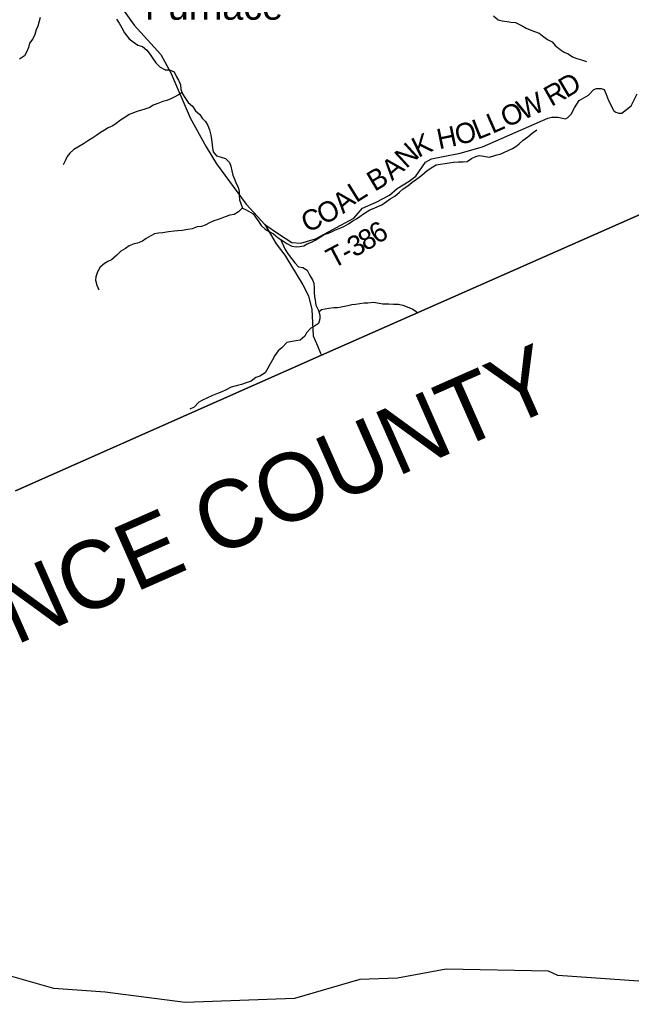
# Model space of a CAD drawing. Extents: x 1624196 to 2029251, y 146837 to 440034.
# Drawn here: x 1885609 to 1894658, y 203742 to 218272 of the extents above; entities that cross this region are included whole.
import ezdxf

# ---------------------------------------------------------------- set-up
doc = ezdxf.new("R2010")
doc.units = 0
for name, color, linetype in [('GM_X_Adjacent_County', 7, 'Continuous'), ('GM_X_Adjacent_County_Text', 7, 'Continuous'), ('GM_X_County', 7, 'Continuous'), ('GM_X_County_Road', 7, 'Continuous'), ('GM_X_Minor_River', 7, 'Continuous'), ('GM_X_Township', 7, 'Continuous'), ('GM_X_Township_Road', 7, 'Continuous'), ('GM_X_Township_Road_Text', 7, 'Continuous'), ('GM_X_Unincorporated_Text', 7, 'Continuous')]:
    doc.layers.add(name, color=color, linetype=linetype)

msp = doc.modelspace()

# ---------------------------------------------------------------- linework, layer by layer
at = {"layer": 'GM_X_Adjacent_County'}
for points in [[(1885546, 211307), (1890073, 213309), (1894505, 215267), (1897042, 216387)], [(1896173, 203954), (1893570, 204139), (1893430, 204203), (1891921, 204231), (1891198, 204101), (1890642, 204079), (1889675, 203798), (1888058, 203742), (1886876, 203894), (1886116, 203945), (1885177, 204215)]]:
    msp.add_lwpolyline(points, dxfattribs=at)
at = {"layer": 'GM_X_County'}
msp.add_lwpolyline([(1897042, 216387), (1894505, 215267), (1890073, 213309), (1885546, 211307)], dxfattribs=at)
at = {"layer": 'GM_X_County_Road'}
msp.add_lwpolyline([(1887156, 218396), (1887302, 218191), (1887700, 217755), (1887844, 217487), (1888132, 216822), (1888368, 216391), (1888519, 216142), (1888958, 215544), (1889237, 215241), (1889405, 214956), (1889532, 214790), (1889797, 214349), (1889882, 214190), (1889930, 213986), (1889950, 213597), (1890016, 213449), (1890062, 213340), (1890073, 213309)], dxfattribs=at)
at = {"layer": 'GM_X_Minor_River'}
for points in [[(1885912, 218306), (1885896, 218250), (1885876, 218178), (1885853, 218124), (1885833, 218054), (1885805, 217990), (1885756, 217925), (1885738, 217859), (1885714, 217801), (1885681, 217737), (1885609, 217689)], [(1887042, 218277), (1887080, 218221), (1887119, 218153), (1887161, 218078), (1887230, 217988), (1887290, 217942), (1887359, 217895), (1887425, 217873), (1887489, 217822), (1887538, 217756), (1887578, 217699), (1887623, 217633), (1887689, 217569), (1887761, 217532), (1887828, 217528), (1887894, 217499), (1887932, 217429), (1887957, 217375), (1887989, 217306), (1887994, 217244), (1888018, 217174), (1888054, 217120), (1888103, 217045), (1888165, 216993), (1888212, 216925), (1888274, 216868), (1888307, 216814), (1888361, 216768), (1888392, 216707), (1888418, 216643), (1888437, 216563), (1888447, 216499), (1888459, 216426), (1888464, 216370), (1888470, 216316), (1888523, 216260), (1888591, 216241), (1888653, 216217), (1888715, 216159), (1888732, 216104), (1888746, 216038), (1888765, 215972), (1888791, 215904), (1888812, 215848), (1888842, 215795), (1888858, 215729), (1888857, 215677), (1888861, 215607), (1888879, 215555), (1888908, 215484), (1888960, 215462), (1889063, 215401), (1889099, 215351), (1889148, 215281), (1889182, 215227), (1889240, 215174), (1889299, 215142), (1889363, 215105), (1889432, 215047), (1889502, 215004), (1889564, 214962), (1889637, 214921), (1889701, 214911), (1889753, 214917), (1889811, 214930), (1889861, 214958), (1889927, 214982), (1889991, 215017), (1890061, 215059), (1890114, 215093), (1890180, 215116)], [(1892617, 218330), (1892689, 218271), (1892747, 218255), (1892822, 218243), (1892876, 218234), (1892942, 218228), (1892994, 218206), (1893052, 218177), (1893103, 218147), (1893163, 218124), (1893223, 218098), (1893293, 218072), (1893344, 218035), (1893416, 217977), (1893485, 217942), (1893531, 217890), (1893605, 217829), (1893662, 217793), (1893722, 217769), (1893788, 217720), (1893853, 217698), (1893921, 217679), (1893993, 217651)], [(1888011, 217196), (1887960, 217162), (1887894, 217127), (1887844, 217103), (1887786, 217077), (1887728, 217062), (1887654, 217034), (1887586, 217006), (1887536, 216973), (1887461, 216949), (1887395, 216930), (1887341, 216912), (1887285, 216890), (1887231, 216868), (1887153, 216817), (1887103, 216787), (1887039, 216739), (1886989, 216704), (1886917, 216674), (1886865, 216636), (1886804, 216603), (1886752, 216565), (1886690, 216527), (1886626, 216484), (1886556, 216438), (1886472, 216388), (1886412, 216353), (1886353, 216299), (1886313, 216247), (1886289, 216193), (1886252, 216123)], [(1890180, 215116), (1890230, 215140), (1890282, 215164), (1890334, 215186), (1890404, 215213), (1890472, 215251), (1890536, 215296), (1890590, 215326), (1890644, 215362), (1890697, 215400), (1890791, 215461), (1890853, 215485), (1890909, 215507), (1890967, 215536), (1891037, 215582), (1891089, 215624), (1891159, 215663), (1891228, 215721), (1891282, 215769), (1891352, 215816), (1891410, 215866), (1891480, 215914), (1891559, 215975), (1891637, 216043), (1891721, 216098), (1891771, 216126), (1891829, 216134), (1891903, 216147), (1891961, 216155), (1892029, 216165), (1892101, 216168), (1892169, 216172), (1892229, 216173), (1892293, 216219), (1892357, 216247), (1892407, 216263), (1892475, 216252), (1892557, 216240), (1892609, 216255), (1892667, 216271), (1892719, 216283), (1892773, 216308), (1892835, 216336), (1892901, 216366), (1892951, 216395), (1893001, 216437), (1893057, 216489), (1893127, 216539), (1893190, 216592), (1893260, 216644)], [(1888905, 215492), (1888848, 215429), (1888782, 215389), (1888720, 215379), (1888650, 215358), (1888598, 215338), (1888546, 215316), (1888480, 215295), (1888420, 215267), (1888355, 215233), (1888297, 215214), (1888237, 215208), (1888163, 215179), (1888097, 215171), (1888012, 215155), (1887948, 215152), (1887894, 215144), (1887810, 215133), (1887726, 215119), (1887664, 215113), (1887606, 215104), (1887548, 215076), (1887480, 215038), (1887426, 214999), (1887355, 214969), (1887303, 214957), (1887231, 214928), (1887177, 214888), (1887107, 214848), (1887047, 214791), (1886967, 214721), (1886915, 214695), (1886864, 214668), (1886802, 214612), (1886762, 214544), (1886735, 214470), (1886733, 214418), (1886749, 214348), (1886780, 214275)], [(1889469, 215024), (1889486, 214980), (1889510, 214926), (1889535, 214874), (1889583, 214804), (1889678, 214675), (1889735, 214616), (1889797, 214606), (1889863, 214566), (1889902, 214491), (1889940, 214427), (1889963, 214375), (1889965, 214305), (1889965, 214238), (1889970, 214176), (1889982, 214124), (1889989, 214052), (1890029, 213974), (1890050, 213903), (1890050, 213849), (1890028, 213781), (1889970, 213740), (1889917, 213710), (1889853, 213642), (1889829, 213590), (1889757, 213535), (1889697, 213523), (1889643, 213513), (1889563, 213496), (1889486, 213420), (1889432, 213376), (1889386, 213307), (1889351, 213241), (1889309, 213173), (1889279, 213119), (1889240, 213051), (1889160, 213003), (1889102, 212982), (1889036, 212926), (1888960, 212900), (1888890, 212879), (1888814, 212857), (1888736, 212836), (1888666, 212798), (1888600, 212770), (1888534, 212743), (1888464, 212717), (1888380, 212674), (1888316, 212648), (1888261, 212614), (1888191, 212540), (1888127, 212511)], [(1890036, 213951), (1890077, 213987), (1890131, 213997), (1890183, 214007), (1890259, 214014), (1890311, 214018), (1890365, 214028), (1890465, 214047), (1890525, 214061), (1890576, 214065), (1890640, 214076), (1890704, 214084), (1890762, 214085), (1890842, 214095), (1890928, 214082), (1890982, 214070), (1891070, 214070), (1891140, 214065), (1891215, 214063), (1891279, 214052), (1891343, 214028), (1891425, 213989), (1891476, 213959), (1891501, 213939)]]:
    msp.add_lwpolyline(points, dxfattribs=at)
at = {"layer": 'GM_X_Township'}
msp.add_lwpolyline([(1897042, 216387), (1894505, 215267), (1890073, 213309), (1885546, 211307)], dxfattribs=at)
at = {"layer": 'GM_X_Township_Road'}
msp.add_lwpolyline([(1889237, 215241), (1889438, 215106), (1889635, 214978), (1889769, 214969), (1889985, 215032), (1890552, 215335), (1890679, 215485), (1890885, 215572), (1891079, 215678), (1891196, 215775), (1891372, 215885), (1891468, 215960), (1891612, 216163), (1891702, 216212), (1891874, 216247), (1892126, 216297), (1892458, 216390), (1893421, 216814), (1893480, 216828), (1893569, 216831), (1893684, 216808), (1893716, 216824), (1893767, 216877), (1893817, 216969), (1893884, 217076), (1894024, 217157), (1894102, 217240), (1894144, 217255), (1894211, 217255), (1894258, 217237), (1894292, 217157), (1894321, 217078), (1894400, 216926), (1894430, 216906), (1894472, 216888), (1894515, 216889), (1894654, 216996), (1894743, 217175)], dxfattribs=at)

# ---------------------------------------------------------------- texts
at = {"layer": 'GM_X_Adjacent_County_Text'}
msp.add_text('LAWRENCE COUNTY', height=1000, rotation=23.826, dxfattribs=at).set_placement((1881198, 207097))
at = {"layer": 'GM_X_Township_Road_Text'}
for s, rotation, p in [('D', 30.7679, (1893696, 217106)), ('R', 29.3165, (1893474, 216981)), ('W', 24.8931, (1893054, 216781)), ('O', 23.8947, (1892808, 216671)), ('L', 21.81, (1892383, 216493)), ('L', 23.8218, (1892602, 216581)), ('H', 11.5811, (1891814, 216354)), ('O', 15.0931, (1892092, 216412)), ('K', 25.8336, (1891504, 216226)), ('N', 42.4353, (1891328, 216061)), ('A', 40.3896, (1891119, 215882)), ('B', 30.6783, (1890861, 215724)), ('L', 32.0358, (1890587, 215558)), ('A', 40.3179, (1890395, 215394)), ('O', 28.3673, (1890106, 215230)), ('C', 23.8917, (1889858, 215119)), ('6', 32.7871, (1890901, 214944)), ('3', 28.7022, (1890559, 214751)), ('8', 30.0519, (1890728, 214843)), ('T', 27.8512, (1890247, 214586)), ('-', 28.0516, (1890447, 214691))]:
    msp.add_text(s, height=300, rotation=rotation, dxfattribs=at).set_placement(p)
at = {"layer": 'GM_X_Unincorporated_Text'}
msp.add_text('Furnace', height=417, rotation=0, dxfattribs=at).set_placement((1887461, 218271))

doc.saveas('drawing.dxf')
